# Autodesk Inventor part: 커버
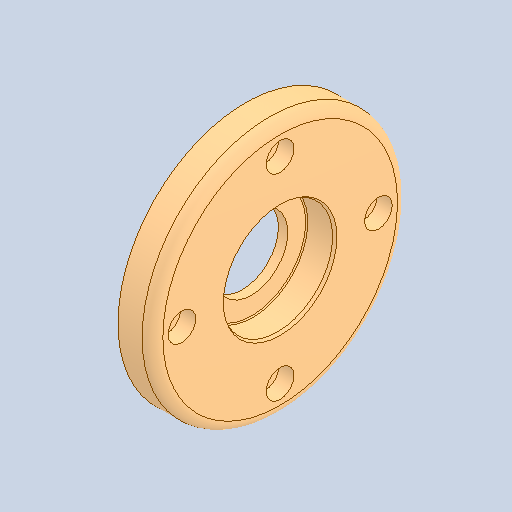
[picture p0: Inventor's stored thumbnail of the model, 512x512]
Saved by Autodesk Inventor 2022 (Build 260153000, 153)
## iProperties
Created: 2024-11
Part Number: 커버
Material: 알루미늄 6061
Document SubType Name: Modeling
Designer: PC-12
Density: 2.7 g/cm^3
Appearance: 기본값
Author: jhkim
Sending System: Autodesk Inventor 2025
Preprocessor: ST-DEVELOPER v20
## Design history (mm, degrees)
node "커버1"
node "솔리드2"
node "솔리드1"
